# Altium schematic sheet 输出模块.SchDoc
size A4; Address1: 张三; Address2: 202311001; Address3: 23应用电子1班
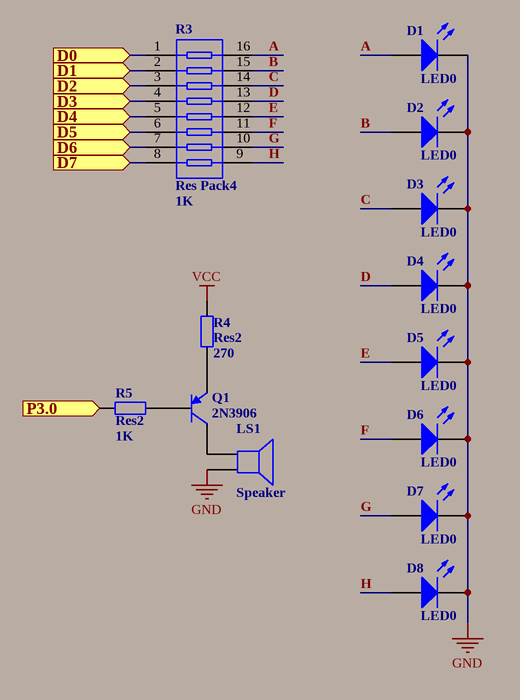
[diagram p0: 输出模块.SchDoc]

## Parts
D1  LED0  [发光二极管]
D2  LED0  [发光二极管]
D3  LED0  [发光二极管]
D4  LED0  [发光二极管]
D5  LED0  [发光二极管]
D6  LED0  [发光二极管]
D7  LED0  [发光二极管]
D8  LED0  [发光二极管]
LS1  Speaker  [PIN2]
Q1  2N3906  [TO-92A]
R3  Res Pack4  value 1K  [DIP-16]
R4  Res2  value 270  [AXIAL-0.4]
R5  Res2  value 1K  [AXIAL-0.4]

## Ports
D0 (in), D1 (in), D2 (in), D3 (in), D4 (in), D5 (in), D6 (in), D7 (in), P3.0 (in)

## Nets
GND: D1.2(K) D2.2(K) D3.2(K) D4.2(K) D5.2(K) D6.2(K) D7.2(K) D8.2(K) LS1.2
VCC: R4.2
A: D1.1(A) R3.16
B: D2.1(A) R3.15
C: D3.1(A) R3.14
D: D4.1(A) R3.13
D0: R3.1 ; port D0
D1: R3.2 ; port D1
D2: R3.3 ; port D2
D3: R3.4 ; port D3
D4: R3.5 ; port D4
D5: R3.6 ; port D5
D6: R3.7 ; port D6
D7: R3.8 ; port D7
E: D5.1(A) R3.12
F: D6.1(A) R3.11
G: D7.1(A) R3.10
H: D8.1(A) R3.9
P3.0: R5.1 ; port P3.0
NetLS1_1: LS1.1 Q1.3(C)
NetQ1_1: Q1.1(E) R4.1
NetQ1_2: Q1.2(B) R5.2

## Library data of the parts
D1-D8 = LED0: Typical INFRARED GaAs LED
LS1 = Speaker: Loudspeaker
Q1 = 2N3906: PNP General Purpose Amplifier
R3 = Res Pack4: Isolated Resistor Network
R4 R5 = Res2: Resistor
